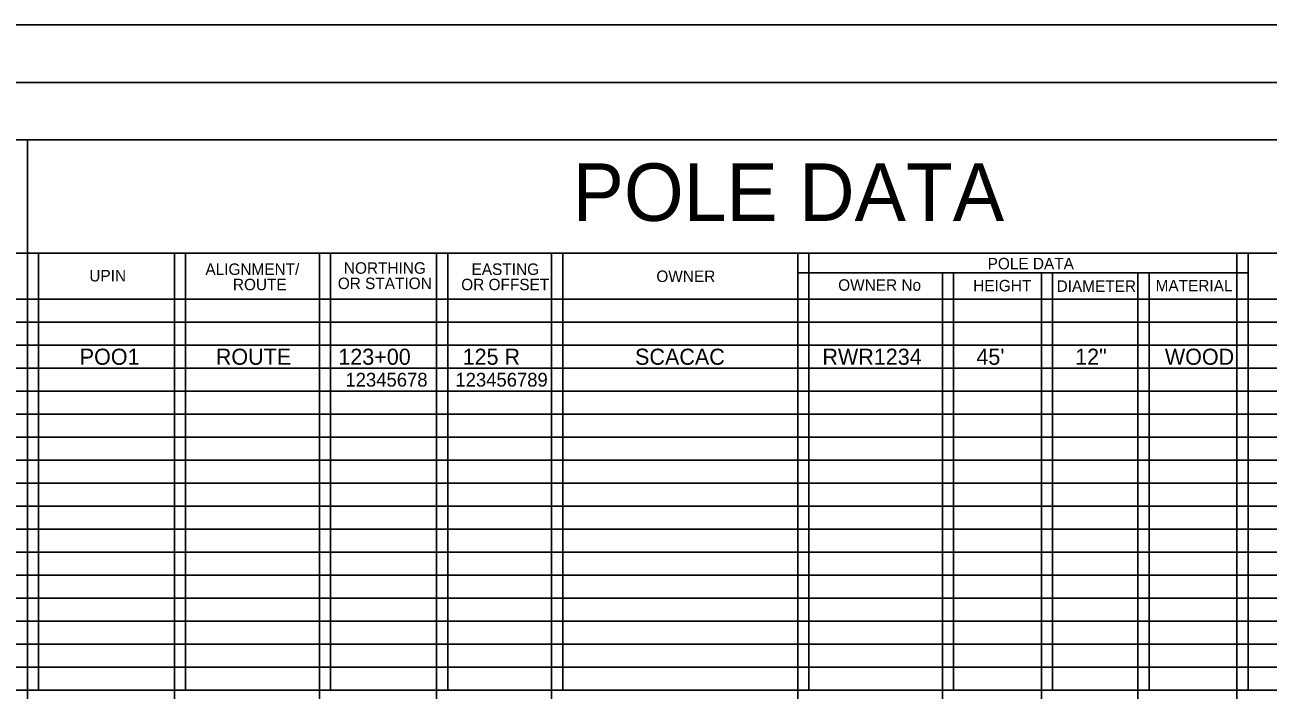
# Model space of a CAD drawing. Extents: x 11473 to 13269, y 16929 to 18079.
# Drawn here: x 12394 to 12935, y 17790 to 18079 of the extents above; entities that cross this region are included whole.
import ezdxf

# ---------------------------------------------------------------- set-up
doc = ezdxf.new("R2010")
doc.units = 0
for name, color, linetype in [('RD_SHT_Bndy', 7, 'Continuous'), ('RD_SHT_Iplotshp', 7, 'Continuous'), ('RD_SHT_Misc2', 7, 'Continuous'), ('RD_SHT_TX', 7, 'Continuous')]:
    doc.layers.add(name, color=color, linetype=linetype)

msp = doc.modelspace()

# ---------------------------------------------------------------- linework, layer by layer
at = {"layer": 'RD_SHT_Bndy'}
for p, q in [((13251.23, 18079.35), (11491.23, 18079.35)), ((13251.23, 18054.35), (11491.23, 18054.35)), ((13248.83, 18029.35), (11573.83, 18029.35))]:
    msp.add_line(p, q, dxfattribs=at)
for points in [[(12399.84, 17960), (12463.82, 17960), (12463.82, 17980), (12399.84, 17980)], [(12463.82, 17960), (12526.83, 17960), (12526.83, 17979.99), (12463.82, 17979.99)], [(12526.83, 17960), (12577.83, 17960), (12577.83, 17980), (12526.83, 17980)], [(12577.83, 17960), (12627.84, 17960), (12627.84, 17979.99), (12577.83, 17979.99)], [(12627.84, 17960), (12734.83, 17960), (12734.83, 17979.97), (12627.84, 17979.97)], [(12734.83, 17979.97), (12925.84, 17979.97), (12925.84, 17971.43), (12734.83, 17971.43)], [(13248.83, 17960), (12925.84, 17960), (12925.84, 17979.97), (13248.83, 17979.97)], [(12734.83, 17960), (12797.82, 17960), (12797.82, 17971.43), (12734.83, 17971.43)], [(12797.82, 17960), (12840.83, 17960), (12840.83, 17971.43), (12797.82, 17971.43)], [(12840.83, 17960), (12882.82, 17960), (12882.82, 17971.43), (12840.83, 17971.43)], [(12882.82, 17960), (12925.84, 17960), (12925.84, 17971.43), (12882.82, 17971.43)], [(12399.84, 17950), (12463.82, 17950), (12463.82, 17960), (12399.84, 17960)], [(12463.82, 17950), (12526.83, 17950), (12526.83, 17960), (12463.82, 17960)], [(12526.83, 17950), (12577.83, 17950), (12577.83, 17960), (12526.83, 17960)], [(12577.83, 17950), (12627.84, 17950), (12627.84, 17960), (12577.83, 17960)], [(12627.84, 17950), (12734.83, 17950), (12734.83, 17960), (12627.84, 17960)], [(12734.83, 17950), (12797.82, 17950), (12797.82, 17960), (12734.83, 17960)], [(12797.82, 17950), (12840.83, 17950), (12840.83, 17960), (12797.82, 17960)], [(12840.83, 17950), (12882.82, 17950), (12882.82, 17960), (12840.83, 17960)], [(12882.82, 17950), (12925.84, 17950), (12925.84, 17960), (12882.82, 17960)], [(12925.84, 17950), (13248.83, 17950), (13248.83, 17960), (12925.84, 17960)], [(12399.84, 17939.99), (12463.82, 17939.99), (12463.82, 17950), (12399.84, 17950)], [(12463.82, 17939.99), (12526.83, 17939.99), (12526.83, 17950), (12463.82, 17950)], [(12526.83, 17939.99), (12577.83, 17939.99), (12577.83, 17950), (12526.83, 17950)], [(12577.83, 17939.99), (12627.84, 17939.99), (12627.84, 17950), (12577.83, 17950)], [(12627.84, 17939.99), (12734.83, 17939.99), (12734.83, 17950), (12627.84, 17950)], [(12734.83, 17939.99), (12797.82, 17939.99), (12797.82, 17950), (12734.83, 17950)], [(12797.82, 17939.99), (12840.83, 17939.99), (12840.83, 17950), (12797.82, 17950)], [(12840.83, 17939.99), (12882.82, 17939.99), (12882.82, 17950), (12840.83, 17950)], [(12882.82, 17939.99), (12925.84, 17939.99), (12925.84, 17950), (12882.82, 17950)], [(12925.84, 17939.99), (13248.83, 17939.99), (13248.83, 17950), (12925.84, 17950)], [(12399.84, 17929.99), (12463.82, 17929.99), (12463.82, 17939.99), (12399.84, 17939.99)], [(12463.82, 17929.99), (12526.83, 17929.99), (12526.83, 17939.99), (12463.82, 17939.99)], [(12526.83, 17929.99), (12577.83, 17929.99), (12577.83, 17939.99), (12526.83, 17939.99)], [(12577.83, 17929.99), (12627.84, 17929.99), (12627.84, 17939.99), (12577.83, 17939.99)], [(12627.84, 17929.99), (12734.83, 17929.99), (12734.83, 17939.99), (12627.84, 17939.99)], [(12734.83, 17929.99), (12797.82, 17929.99), (12797.82, 17939.99), (12734.83, 17939.99)], [(12797.82, 17929.99), (12840.83, 17929.99), (12840.83, 17939.99), (12797.82, 17939.99)], [(12840.83, 17929.99), (12882.82, 17929.99), (12882.82, 17939.99), (12840.83, 17939.99)], [(12882.82, 17929.99), (12925.84, 17929.99), (12925.84, 17939.99), (12882.82, 17939.99)], [(12925.84, 17929.99), (13248.83, 17929.99), (13248.83, 17939.99), (12925.84, 17939.99)], [(12399.84, 17919.99), (12463.82, 17919.99), (12463.82, 17929.99), (12399.84, 17929.99)], [(12463.82, 17919.99), (12526.83, 17919.99), (12526.83, 17929.99), (12463.82, 17929.99)], [(12526.83, 17919.99), (12577.83, 17919.99), (12577.83, 17929.99), (12526.83, 17929.99)], [(12577.83, 17919.99), (12627.84, 17919.99), (12627.84, 17929.99), (12577.83, 17929.99)], [(12627.84, 17919.99), (12734.83, 17919.99), (12734.83, 17929.99), (12627.84, 17929.99)], [(12734.83, 17919.99), (12797.82, 17919.99), (12797.82, 17929.99), (12734.83, 17929.99)], [(12797.82, 17919.99), (12840.83, 17919.99), (12840.83, 17929.99), (12797.82, 17929.99)], [(12840.83, 17919.99), (12882.82, 17919.99), (12882.82, 17929.99), (12840.83, 17929.99)], [(12882.82, 17919.99), (12925.84, 17919.99), (12925.84, 17929.99), (12882.82, 17929.99)], [(12925.84, 17919.99), (13248.83, 17919.99), (13248.83, 17929.99), (12925.84, 17929.99)], [(12399.84, 17909.98), (12463.82, 17909.98), (12463.82, 17919.99), (12399.84, 17919.99)], [(12463.82, 17909.98), (12526.83, 17909.98), (12526.83, 17919.99), (12463.82, 17919.99)], [(12526.83, 17909.98), (12577.83, 17909.98), (12577.83, 17919.99), (12526.83, 17919.99)], [(12577.83, 17909.98), (12627.84, 17909.98), (12627.84, 17919.99), (12577.83, 17919.99)], [(12627.84, 17909.98), (12734.83, 17909.98), (12734.83, 17919.99), (12627.84, 17919.99)], [(12734.83, 17909.98), (12797.82, 17909.98), (12797.82, 17919.99), (12734.83, 17919.99)], [(12797.82, 17909.98), (12840.83, 17909.98), (12840.83, 17919.99), (12797.82, 17919.99)], [(12840.83, 17909.98), (12882.82, 17909.98), (12882.82, 17919.99), (12840.83, 17919.99)], [(12882.82, 17909.98), (12925.84, 17909.98), (12925.84, 17919.99), (12882.82, 17919.99)], [(12925.84, 17909.98), (13248.83, 17909.98), (13248.83, 17919.99), (12925.84, 17919.99)], [(12399.84, 17899.98), (12463.82, 17899.98), (12463.82, 17909.98), (12399.84, 17909.98)], [(12463.82, 17899.98), (12526.83, 17899.98), (12526.83, 17909.98), (12463.82, 17909.98)], [(12526.83, 17899.98), (12577.83, 17899.98), (12577.83, 17909.98), (12526.83, 17909.98)], [(12577.83, 17899.98), (12627.84, 17899.98), (12627.84, 17909.98), (12577.83, 17909.98)], [(12627.84, 17899.98), (12734.83, 17899.98), (12734.83, 17909.98), (12627.84, 17909.98)], [(12734.83, 17899.98), (12797.82, 17899.98), (12797.82, 17909.98), (12734.83, 17909.98)], [(12797.82, 17899.98), (12840.83, 17899.98), (12840.83, 17909.98), (12797.82, 17909.98)], [(12840.83, 17899.98), (12882.82, 17899.98), (12882.82, 17909.98), (12840.83, 17909.98)], [(12882.82, 17899.98), (12925.84, 17899.98), (12925.84, 17909.98), (12882.82, 17909.98)], [(12925.84, 17899.98), (13248.83, 17899.98), (13248.83, 17909.98), (12925.84, 17909.98)], [(12399.84, 17889.97), (12463.82, 17889.97), (12463.82, 17899.98), (12399.84, 17899.98)], [(12463.82, 17889.97), (12526.83, 17889.97), (12526.83, 17899.98), (12463.82, 17899.98)], [(12526.83, 17889.97), (12577.83, 17889.97), (12577.83, 17899.98), (12526.83, 17899.98)], [(12577.83, 17889.97), (12627.84, 17889.97), (12627.84, 17899.98), (12577.83, 17899.98)], [(12627.84, 17889.97), (12734.83, 17889.97), (12734.83, 17899.98), (12627.84, 17899.98)], [(12734.83, 17889.97), (12797.82, 17889.97), (12797.82, 17899.98), (12734.83, 17899.98)], [(12797.82, 17889.97), (12840.83, 17889.97), (12840.83, 17899.98), (12797.82, 17899.98)], [(12840.83, 17889.97), (12882.82, 17889.97), (12882.82, 17899.98), (12840.83, 17899.98)], [(12882.82, 17889.97), (12925.84, 17889.97), (12925.84, 17899.98), (12882.82, 17899.98)], [(12925.84, 17889.97), (13248.83, 17889.97), (13248.83, 17899.98), (12925.84, 17899.98)], [(12399.84, 17879.97), (12463.82, 17879.97), (12463.82, 17889.97), (12399.84, 17889.97)], [(12463.82, 17879.97), (12526.83, 17879.97), (12526.83, 17889.97), (12463.82, 17889.97)], [(12526.83, 17879.97), (12577.83, 17879.97), (12577.83, 17889.97), (12526.83, 17889.97)], [(12577.83, 17879.97), (12627.84, 17879.97), (12627.84, 17889.97), (12577.83, 17889.97)], [(12627.84, 17879.97), (12734.83, 17879.97), (12734.83, 17889.97), (12627.84, 17889.97)], [(12734.83, 17879.97), (12797.82, 17879.97), (12797.82, 17889.97), (12734.83, 17889.97)], [(12797.82, 17879.97), (12840.83, 17879.97), (12840.83, 17889.97), (12797.82, 17889.97)], [(12840.83, 17879.97), (12882.82, 17879.97), (12882.82, 17889.97), (12840.83, 17889.97)], [(12882.82, 17879.97), (12925.84, 17879.97), (12925.84, 17889.97), (12882.82, 17889.97)], [(12925.84, 17879.97), (13248.83, 17879.97), (13248.83, 17889.97), (12925.84, 17889.97)], [(12399.84, 17869.96), (12463.82, 17869.96), (12463.82, 17879.97), (12399.84, 17879.97)], [(12463.82, 17869.96), (12526.83, 17869.96), (12526.83, 17879.97), (12463.82, 17879.97)], [(12526.83, 17869.96), (12577.83, 17869.96), (12577.83, 17879.97), (12526.83, 17879.97)], [(12577.83, 17869.96), (12627.84, 17869.96), (12627.84, 17879.97), (12577.83, 17879.97)], [(12627.84, 17869.96), (12734.83, 17869.96), (12734.83, 17879.97), (12627.84, 17879.97)], [(12734.83, 17869.96), (12797.82, 17869.96), (12797.82, 17879.97), (12734.83, 17879.97)], [(12797.82, 17869.96), (12840.83, 17869.96), (12840.83, 17879.97), (12797.82, 17879.97)], [(12840.83, 17869.96), (12882.82, 17869.96), (12882.82, 17879.97), (12840.83, 17879.97)], [(12882.82, 17869.96), (12925.84, 17869.96), (12925.84, 17879.97), (12882.82, 17879.97)], [(12925.84, 17869.96), (13248.83, 17869.96), (13248.83, 17879.97), (12925.84, 17879.97)], [(12399.84, 17859.96), (12463.82, 17859.96), (12463.82, 17869.96), (12399.84, 17869.96)], [(12463.82, 17859.96), (12526.83, 17859.96), (12526.83, 17869.96), (12463.82, 17869.96)], [(12526.83, 17859.96), (12577.83, 17859.96), (12577.83, 17869.96), (12526.83, 17869.96)], [(12577.83, 17859.96), (12627.84, 17859.96), (12627.84, 17869.96), (12577.83, 17869.96)], [(12627.84, 17859.96), (12734.83, 17859.96), (12734.83, 17869.96), (12627.84, 17869.96)], [(12734.83, 17859.96), (12797.82, 17859.96), (12797.82, 17869.96), (12734.83, 17869.96)], [(12797.82, 17859.96), (12840.83, 17859.96), (12840.83, 17869.96), (12797.82, 17869.96)], [(12840.83, 17859.96), (12882.82, 17859.96), (12882.82, 17869.96), (12840.83, 17869.96)], [(12882.82, 17859.96), (12925.84, 17859.96), (12925.84, 17869.96), (12882.82, 17869.96)], [(12925.84, 17859.96), (13248.83, 17859.96), (13248.83, 17869.96), (12925.84, 17869.96)], [(12399.84, 17849.96), (12463.82, 17849.96), (12463.82, 17859.96), (12399.84, 17859.96)], [(12463.82, 17849.96), (12526.83, 17849.96), (12526.83, 17859.96), (12463.82, 17859.96)], [(12526.83, 17849.96), (12577.83, 17849.96), (12577.83, 17859.96), (12526.83, 17859.96)], [(12577.83, 17849.96), (12627.84, 17849.96), (12627.84, 17859.96), (12577.83, 17859.96)], [(12627.84, 17849.96), (12734.83, 17849.96), (12734.83, 17859.96), (12627.84, 17859.96)], [(12734.83, 17849.96), (12797.82, 17849.96), (12797.82, 17859.96), (12734.83, 17859.96)], [(12797.82, 17849.96), (12840.83, 17849.96), (12840.83, 17859.96), (12797.82, 17859.96)], [(12840.83, 17849.96), (12882.82, 17849.96), (12882.82, 17859.96), (12840.83, 17859.96)], [(12882.82, 17849.96), (12925.84, 17849.96), (12925.84, 17859.96), (12882.82, 17859.96)], [(12925.84, 17849.96), (13248.83, 17849.96), (13248.83, 17859.96), (12925.84, 17859.96)], [(12399.84, 17839.95), (12463.82, 17839.95), (12463.82, 17849.96), (12399.84, 17849.96)], [(12463.82, 17839.95), (12526.83, 17839.95), (12526.83, 17849.96), (12463.82, 17849.96)], [(12526.83, 17839.95), (12577.83, 17839.95), (12577.83, 17849.96), (12526.83, 17849.96)], [(12577.83, 17839.95), (12627.84, 17839.95), (12627.84, 17849.96), (12577.83, 17849.96)], [(12627.84, 17839.95), (12734.83, 17839.95), (12734.83, 17849.96), (12627.84, 17849.96)], [(12734.83, 17839.95), (12797.82, 17839.95), (12797.82, 17849.96), (12734.83, 17849.96)], [(12797.82, 17839.95), (12840.83, 17839.95), (12840.83, 17849.96), (12797.82, 17849.96)], [(12840.83, 17839.95), (12882.82, 17839.95), (12882.82, 17849.96), (12840.83, 17849.96)], [(12882.82, 17839.95), (12925.84, 17839.95), (12925.84, 17849.96), (12882.82, 17849.96)], [(12925.84, 17839.95), (13248.83, 17839.95), (13248.83, 17849.96), (12925.84, 17849.96)], [(12399.84, 17829.95), (12463.82, 17829.95), (12463.82, 17839.95), (12399.84, 17839.95)], [(12463.82, 17829.95), (12526.83, 17829.95), (12526.83, 17839.95), (12463.82, 17839.95)], [(12526.83, 17829.95), (12577.83, 17829.95), (12577.83, 17839.95), (12526.83, 17839.95)], [(12577.83, 17829.95), (12627.84, 17829.95), (12627.84, 17839.95), (12577.83, 17839.95)], [(12627.84, 17829.95), (12734.83, 17829.95), (12734.83, 17839.95), (12627.84, 17839.95)], [(12734.83, 17829.95), (12797.82, 17829.95), (12797.82, 17839.95), (12734.83, 17839.95)], [(12797.82, 17829.95), (12840.83, 17829.95), (12840.83, 17839.95), (12797.82, 17839.95)], [(12840.83, 17829.95), (12882.82, 17829.95), (12882.82, 17839.95), (12840.83, 17839.95)], [(12882.82, 17829.95), (12925.84, 17829.95), (12925.84, 17839.95), (12882.82, 17839.95)], [(12925.84, 17829.95), (13248.83, 17829.95), (13248.83, 17839.95), (12925.84, 17839.95)], [(12399.84, 17819.94), (12463.82, 17819.94), (12463.82, 17829.95), (12399.84, 17829.95)], [(12463.82, 17819.94), (12526.83, 17819.94), (12526.83, 17829.95), (12463.82, 17829.95)], [(12526.83, 17819.94), (12577.83, 17819.94), (12577.83, 17829.95), (12526.83, 17829.95)], [(12577.83, 17819.94), (12627.84, 17819.94), (12627.84, 17829.95), (12577.83, 17829.95)], [(12627.84, 17819.94), (12734.83, 17819.94), (12734.83, 17829.95), (12627.84, 17829.95)], [(12734.83, 17819.94), (12797.82, 17819.94), (12797.82, 17829.95), (12734.83, 17829.95)], [(12797.82, 17819.94), (12840.83, 17819.94), (12840.83, 17829.95), (12797.82, 17829.95)], [(12840.83, 17819.94), (12882.82, 17819.94), (12882.82, 17829.95), (12840.83, 17829.95)], [(12882.82, 17819.94), (12925.84, 17819.94), (12925.84, 17829.95), (12882.82, 17829.95)], [(12925.84, 17819.94), (13248.83, 17819.94), (13248.83, 17829.95), (12925.84, 17829.95)], [(12399.84, 17809.94), (12463.82, 17809.94), (12463.82, 17819.94), (12399.84, 17819.94)], [(12463.82, 17809.94), (12526.83, 17809.94), (12526.83, 17819.94), (12463.82, 17819.94)], [(12526.83, 17809.94), (12577.83, 17809.94), (12577.83, 17819.94), (12526.83, 17819.94)], [(12577.83, 17809.94), (12627.84, 17809.94), (12627.84, 17819.94), (12577.83, 17819.94)], [(12627.84, 17809.94), (12734.83, 17809.94), (12734.83, 17819.94), (12627.84, 17819.94)], [(12734.83, 17809.94), (12797.82, 17809.94), (12797.82, 17819.94), (12734.83, 17819.94)], [(12797.82, 17809.94), (12840.83, 17809.94), (12840.83, 17819.94), (12797.82, 17819.94)], [(12840.83, 17809.94), (12882.82, 17809.94), (12882.82, 17819.94), (12840.83, 17819.94)], [(12882.82, 17809.94), (12925.84, 17809.94), (12925.84, 17819.94), (12882.82, 17819.94)], [(12925.84, 17809.94), (13248.83, 17809.94), (13248.83, 17819.94), (12925.84, 17819.94)], [(12399.84, 17799.93), (12463.82, 17799.93), (12463.82, 17809.94), (12399.84, 17809.94)], [(12463.82, 17799.93), (12526.83, 17799.93), (12526.83, 17809.94), (12463.82, 17809.94)], [(12526.83, 17799.93), (12577.83, 17799.93), (12577.83, 17809.94), (12526.83, 17809.94)], [(12577.83, 17799.93), (12627.84, 17799.93), (12627.84, 17809.94), (12577.83, 17809.94)], [(12627.84, 17799.93), (12734.83, 17799.93), (12734.83, 17809.94), (12627.84, 17809.94)], [(12734.83, 17799.93), (12797.82, 17799.93), (12797.82, 17809.94), (12734.83, 17809.94)], [(12797.82, 17799.93), (12840.83, 17799.93), (12840.83, 17809.94), (12797.82, 17809.94)], [(12840.83, 17799.93), (12882.82, 17799.93), (12882.82, 17809.94), (12840.83, 17809.94)], [(12882.82, 17799.93), (12925.84, 17799.93), (12925.84, 17809.94), (12882.82, 17809.94)], [(12925.84, 17799.93), (13248.83, 17799.93), (13248.83, 17809.94), (12925.84, 17809.94)], [(12399.84, 17789.93), (12463.82, 17789.93), (12463.82, 17799.93), (12399.84, 17799.93)], [(12463.82, 17789.93), (12526.83, 17789.93), (12526.83, 17799.93), (12463.82, 17799.93)], [(12526.83, 17789.93), (12577.83, 17789.93), (12577.83, 17799.93), (12526.83, 17799.93)], [(12577.83, 17789.93), (12627.84, 17789.93), (12627.84, 17799.93), (12577.83, 17799.93)], [(12627.84, 17789.93), (12734.83, 17789.93), (12734.83, 17799.93), (12627.84, 17799.93)], [(12734.83, 17789.93), (12797.82, 17789.93), (12797.82, 17799.93), (12734.83, 17799.93)], [(12797.82, 17789.93), (12840.83, 17789.93), (12840.83, 17799.93), (12797.82, 17799.93)], [(12840.83, 17789.93), (12882.82, 17789.93), (12882.82, 17799.93), (12840.83, 17799.93)], [(12882.82, 17789.93), (12925.84, 17789.93), (12925.84, 17799.93), (12882.82, 17799.93)], [(12925.84, 17789.93), (13248.83, 17789.93), (13248.83, 17799.93), (12925.84, 17799.93)]]:
    msp.add_lwpolyline(points, close=True, dxfattribs=at)
at = {"layer": 'RD_SHT_Iplotshp'}
msp.add_lwpolyline([(11472.63, 18054.35), (13268.63, 18054.35), (13268.63, 16954.35), (11472.63, 16954.35)], close=True, dxfattribs=at)
at = {"layer": 'RD_SHT_Misc2'}
for p, q in [((12395.01, 18029.35), (12395.01, 17110)), ((11576, 17979.97), (13244, 17979.97)), ((12458.99, 17980), (12458.99, 17110)), ((12522, 17979.99), (12522, 17110)), ((12573, 17980), (12573, 17110)), ((12623.01, 17979.99), (12623.01, 17110)), ((12730, 17979.97), (12730, 17110)), ((12921.01, 17979.97), (12921.01, 17110)), ((12730, 17971.43), (12921.01, 17971.43)), ((12792.98, 17971.05), (12792.98, 17110)), ((12836, 17971.43), (12836, 17110)), ((12877.99, 17971.43), (12877.99, 17110)), ((11576, 17960), (13244, 17960)), ((11576, 17950), (13244, 17950)), ((11576, 17940), (13244, 17940)), ((11576, 17930), (13244, 17930)), ((11576, 17920), (13244, 17920)), ((11576, 17910), (13244, 17910)), ((11576, 17900), (13244, 17900)), ((11576, 17890), (13244, 17890)), ((11576, 17880), (13244, 17880)), ((11576, 17870), (13244, 17870)), ((11576, 17860), (13244, 17860)), ((11576, 17850), (13244, 17850)), ((11576, 17840), (13244, 17840)), ((11576, 17830), (13244, 17830)), ((11576, 17820), (13244, 17820)), ((11576, 17810), (13244, 17810)), ((11576, 17800), (13244, 17800)), ((11576, 17790), (13244, 17790))]:
    msp.add_line(p, q, dxfattribs=at)

# ---------------------------------------------------------------- texts
at = {"layer": 'RD_SHT_TX'}
for s, height, p in [('POLE DATA', 25, (12632.13, 17994.08)), ('POLE DATA', 5, (12812.59, 17972.99)), ('UPIN', 5, (12421.96, 17967.75)), ('ALIGNMENT/', 5, (12472.43, 17970.57)), ('NORTHING', 5, (12532.66, 17971.08)), ('EASTING', 5, (12588.18, 17970.57)), ('OWNER', 5, (12668.55, 17967.49)), ('ROUTE', 5, (12484.39, 17963.91)), ('OR STATION', 5, (12530.01, 17964.41)), ('OR OFFSET', 5, (12583.69, 17963.91)), ('OWNER No', 5, (12747.62, 17963.68)), ('HEIGHT', 5, (12806.32, 17963.41)), ('DIAMETER', 5, (12842.59, 17963.22)), ('MATERIAL', 5, (12885.65, 17963.41)), ('POO1', 7, (12417.78, 17931.49)), ('ROUTE', 7, (12476.97, 17931.49)), ('123+00', 7, (12530.23, 17931.49)), ('125 R', 7, (12584.29, 17931.49)), ('SCACAC', 7, (12659.29, 17931.49)), ('RWR1234', 7, (12740.75, 17931.49)), ("45'", 7, (12807.72, 17931.49)), ('12"', 7, (12850.67, 17931.49)), ('WOOD', 7, (12889.67, 17931.49)), ('12345678', 6, (12533.34, 17921.99)), ('123456789', 6, (12581.15, 17921.99))]:
    msp.add_text(s, height=height, dxfattribs=at).set_placement(p)

doc.saveas('drawing.dxf')
